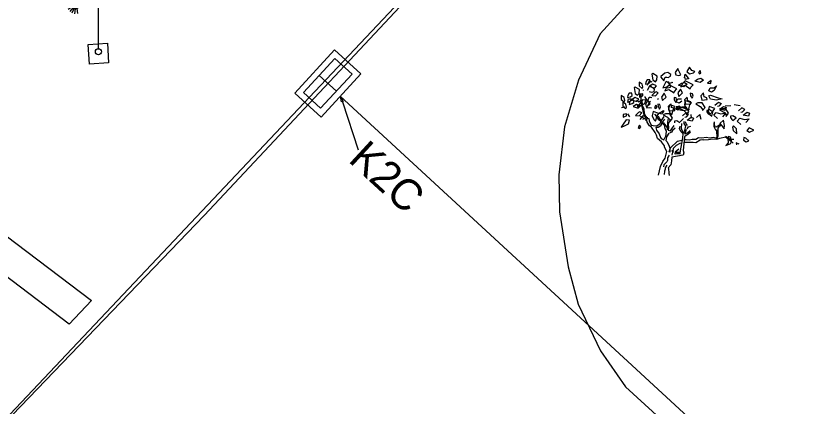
# Model space of a CAD drawing. Extents: x 343997 to 344255, y 298512 to 298767.
# Drawn here: x 344085.39 to 344111.1, y 298717.85 to 298730.51 of the extents above; entities that cross this region are included whole.
import ezdxf

# ---------------------------------------------------------------- set-up
doc = ezdxf.new("R2010")
doc.units = 0
for name, color, linetype in [('Default', 7, 'Continuous'), ('DH_CADRE-CARTOUCHE', 7, 'Continuous'), ('DIR-Projet VRD1', 7, 'Continuous'), ('GO_DALLE', 7, 'Continuous'), ('O-Projet New VRD', 7, 'Continuous'), ('PC_REBAR', 7, 'Continuous'), ('RES_ELECTRICITE', 7, 'Continuous')]:
    doc.layers.add(name, color=color, linetype=linetype)

# ---------------------------------------------------------------- blocks, each defined once
blk = doc.blocks.new('EDF1')
at = {"layer": 'Default'}
for points in [[(-0.0855, 0.1462), (-0.0985, 0.1373)], [(-0.083, 0.1422), (-0.0931, 0.1303)], [(-0.0793, 0.1397), (-0.086, 0.1257)], [(-0.0753, 0.1388), (-0.0781, 0.1235)], [(-0.0701, 0.14), (-0.0684, 0.1241)], [(0, 0.01), (0, 0.15)]]:
    blk.add_lwpolyline(points, dxfattribs=at)
for centre, radius in [((-0.075, 0.15), 0.0112), ((0, 0), 0.01)]:
    blk.add_circle(centre, radius, dxfattribs=at)
blk.add_arc((-0.035, 0.155), 0.0354, 351.8699, 171.8699, dxfattribs=at)
blk = doc.blocks.new('FLAMBOY')
at = {"layer": 'Default'}
for p, q in [((-0.0832, 0.3464), (-0.0832, 0.3442)), ((-0.0238, 0.3069), (-0.0213, 0.3132)), ((-0.157, 0.2764), (-0.1707, 0.2742)), ((0.2497, 0.2813), (0.2722, 0.2832)), ((0.3097, 0.2813), (0.2859, 0.2854)), ((-0.1371, 0.2378), (-0.1446, 0.2497)), ((0.0808, 0.2303), (0.0671, 0.2171)), ((0.0866, 0.1688), (0.0866, 0.1688)), ((0.0407, 0.0927), (0.0337, 0.1011))]:
    blk.add_line(p, q, dxfattribs=at)
for points in [[(0.0617, 0.4053), (0.0692, 0.4072), (0.0592, 0.4288), (0.0579, 0.4328), (0.0467, 0.4172), (0.0492, 0.4072)], [(0.1054, 0.4113), (0.1204, 0.415), (0.1267, 0.4213), (0.1142, 0.425), (0.1054, 0.4388), (0.0942, 0.4213)], [(0.1504, 0.415), (0.1479, 0.425), (0.1417, 0.4172), (0.1454, 0.4113)], [(-0.0621, 0.3722), (-0.0546, 0.3772), (-0.0558, 0.3872), (-0.0671, 0.3872), (-0.0721, 0.3772), (-0.0733, 0.3691)], [(-0.0471, 0.4106), (-0.0433, 0.3866), (-0.0333, 0.3791), (-0.0271, 0.3866), (-0.0258, 0.4025), (-0.0433, 0.4122)], [(0.0054, 0.4141), (-0.0108, 0.4006), (-0.0108, 0.3985), (0.0004, 0.3825), (0.0042, 0.3906), (0.0067, 0.3985), (0.0129, 0.3985), (0.0179, 0.3966), (0.0279, 0.4025), (0.0292, 0.4085), (0.0167, 0.4163)], [(0.0892, 0.3891), (0.0867, 0.395), (0.0842, 0.395), (0.0867, 0.4106), (0.0979, 0.395), (0.1017, 0.3928)], [(0.1504, 0.3938), (0.1617, 0.3863), (0.1479, 0.3763), (0.1267, 0.3822), (0.1379, 0.39)], [(-0.1195, 0.3564), (-0.1157, 0.3324), (-0.1057, 0.3249), (-0.0995, 0.3324), (-0.0982, 0.3483), (-0.1157, 0.358)], [(-0.0846, 0.3581), (-0.0871, 0.3697), (-0.0996, 0.3775), (-0.0996, 0.3622), (-0.0871, 0.3522)], [(-0.0433, 0.3691), (-0.0571, 0.361), (-0.0408, 0.355), (-0.0358, 0.355), (-0.0283, 0.3631)], [(0.0292, 0.3644), (0.0254, 0.3685), (0.0129, 0.3803), (0.0079, 0.3763), (-0.0008, 0.3606), (-0.0033, 0.3547), (0.0079, 0.3569), (0.0167, 0.3547), (0.0279, 0.3569)], [(0.0533, 0.35), (0.0371, 0.3581), (0.0221, 0.3656), (0.0121, 0.3562), (0.0046, 0.3421), (0.0208, 0.3481), (0.0421, 0.334), (0.0446, 0.3403)], [(0.0958, 0.3693), (0.0821, 0.3593), (0.0608, 0.3653), (0.0721, 0.3731), (0.0846, 0.3768)], [(0.1192, 0.3669), (0.1029, 0.375), (0.0879, 0.3825), (0.0779, 0.3731), (0.0704, 0.3591), (0.0867, 0.365), (0.1079, 0.351), (0.1104, 0.3572)], [(0.1779, 0.3738), (0.1917, 0.3716), (0.1929, 0.3838)], [(0.1829, 0.3422), (0.1892, 0.3541), (0.2042, 0.3541), (0.2142, 0.3622), (0.2054, 0.3441), (0.1942, 0.3366)], [(-0.172, 0.308), (-0.1595, 0.298), (-0.157, 0.3039), (-0.1595, 0.3155), (-0.172, 0.3233)], [(-0.1345, 0.318), (-0.127, 0.323), (-0.1282, 0.333), (-0.1395, 0.333), (-0.1445, 0.323), (-0.1457, 0.3149)], [(-0.0983, 0.3285), (-0.0983, 0.3166), (-0.0846, 0.3225), (-0.0846, 0.3306)], [(-0.0308, 0.3388), (-0.0358, 0.336), (-0.0483, 0.3241), (-0.0333, 0.3225), (-0.0221, 0.3341)], [(0.0108, 0.3168), (0.0021, 0.3325), (-0.0079, 0.3168), (-0.0042, 0.3031)], [(0.0767, 0.3338), (0.0679, 0.3494), (0.0579, 0.3338), (0.0617, 0.32)], [(0.1167, 0.3306), (0.1079, 0.3325), (0.1092, 0.3225), (0.1154, 0.3125), (0.1192, 0.3206)], [(0.1767, 0.3069), (0.1754, 0.3147), (0.1642, 0.3185), (0.1617, 0.3344), (0.1504, 0.3225), (0.1542, 0.305)], [(0.1829, 0.3225), (0.1904, 0.3244), (0.2204, 0.3147), (0.2367, 0.3106), (0.2142, 0.305), (0.1904, 0.3091)], [(-0.1504, 0.2768), (-0.1529, 0.2884), (-0.1654, 0.2962), (-0.1654, 0.2809), (-0.1529, 0.2709)], [(-0.1421, 0.3103), (-0.1308, 0.3103), (-0.1296, 0.3038), (-0.1446, 0.2953)], [(-0.1392, 0.2878), (-0.1279, 0.2909), (-0.1204, 0.2959), (-0.1217, 0.3059), (-0.1329, 0.3059), (-0.1379, 0.2959)], [(-0.1132, 0.3008), (-0.1082, 0.3008), (-0.1007, 0.3089), (-0.1157, 0.3149), (-0.1295, 0.3067)], [(-0.0958, 0.281), (-0.0758, 0.2906), (-0.0721, 0.3047), (-0.0858, 0.3066), (-0.0983, 0.2888), (-0.1058, 0.2772)], [(-0.07, 0.276), (-0.055, 0.2897), (-0.0638, 0.3053), (-0.0738, 0.2897)], [(0.03, 0.2903), (0.0187, 0.2785), (0.0225, 0.261), (0.045, 0.2628), (0.0437, 0.2707), (0.0325, 0.2744)], [(0.0508, 0.3137), (0.0421, 0.3156), (0.0433, 0.3056), (0.0496, 0.2956), (0.0533, 0.3037)], [(0.1108, 0.29), (0.1096, 0.2978), (0.0983, 0.3015), (0.0958, 0.3175), (0.0846, 0.3056), (0.0883, 0.2881)], [(0.1117, 0.2953), (0.1054, 0.2853), (0.0992, 0.2638), (0.0917, 0.2697), (0.0854, 0.2853), (0.0892, 0.3028)], [(0.1679, 0.2756), (0.1567, 0.2938), (0.1392, 0.2938), (0.1304, 0.2897), (0.1479, 0.2797), (0.1567, 0.27), (0.1579, 0.2622)], [(-0.1092, 0.2878), (-0.1229, 0.2796), (-0.1067, 0.2737), (-0.1017, 0.2737), (-0.0942, 0.2818)], [(-0.0967, 0.2574), (-0.1017, 0.2546), (-0.1142, 0.2428), (-0.0992, 0.2412), (-0.0879, 0.2528)], [(-0.0263, 0.2413), (-0.02, 0.2513), (-0.0425, 0.2588), (-0.0463, 0.2413), (-0.04, 0.2257), (-0.0325, 0.2197)], [(-0.0258, 0.2775), (-0.0321, 0.2841), (-0.0371, 0.2756), (-0.0321, 0.2706)], [(-0.015, 0.2866), (-0.0238, 0.2885), (-0.0225, 0.2785), (-0.0163, 0.2685), (-0.0125, 0.2766)], [(-0.0079, 0.2484), (-0.0179, 0.2525), (-0.0004, 0.2631), (-0.0004, 0.2584)], [(0.0396, 0.2684), (0.0458, 0.2784), (0.0233, 0.2859), (0.0196, 0.2684), (0.0258, 0.2528), (0.0333, 0.2468)], [(0.0579, 0.2653), (0.0654, 0.2753), (0.0654, 0.28), (0.0479, 0.2694)], [(0.0512, 0.2785), (0.0587, 0.2803), (0.0887, 0.2707), (0.105, 0.2666), (0.0825, 0.261), (0.0587, 0.265)], [(0.0733, 0.2768), (0.0646, 0.2728), (0.0821, 0.2628), (0.0908, 0.2531), (0.0921, 0.2453), (0.1021, 0.2587), (0.0908, 0.2768)], [(0.1804, 0.2497), (0.1854, 0.246), (0.1979, 0.2569), (0.1854, 0.2653), (0.1754, 0.2635), (0.1754, 0.2575)], [(0.2009, 0.2616), (0.2072, 0.2716), (0.1847, 0.2791), (0.1809, 0.2616), (0.1872, 0.246), (0.1947, 0.24)], [(0.2522, 0.27), (0.2347, 0.27), (0.2259, 0.266), (0.2434, 0.256), (0.2522, 0.2463), (0.2534, 0.2385), (0.2634, 0.2519)], [(0.2479, 0.2635), (0.2267, 0.2678), (0.2429, 0.2794), (0.2529, 0.2753)], [(-0.1617, 0.1996), (-0.1417, 0.2093), (-0.1379, 0.2234), (-0.1517, 0.2253), (-0.1642, 0.2074), (-0.1717, 0.1959)], [(-0.1642, 0.2471), (-0.1642, 0.2353), (-0.1504, 0.2412), (-0.1504, 0.2493)], [(0.0075, 0.2497), (-0.0013, 0.2457), (0.0162, 0.2357), (0.025, 0.226), (0.0262, 0.2182), (0.0362, 0.2316), (0.025, 0.2497)], [(0.1112, 0.2353), (0.1212, 0.2313), (0.1162, 0.2194), (0.095, 0.2238)], [(0.2759, 0.226), (0.2809, 0.2222), (0.2934, 0.2332), (0.2809, 0.2416), (0.2709, 0.2397), (0.2709, 0.2338)], [(0.3484, 0.2516), (0.3434, 0.2397), (0.3222, 0.2441), (0.3384, 0.2557)], [(-0.0917, 0.1962), (-0.0979, 0.2028), (-0.1029, 0.1943), (-0.0979, 0.1893)], [(0.2284, 0.2104), (0.2359, 0.2007), (0.2447, 0.1888), (0.2472, 0.2025), (0.2422, 0.2235)], [(0.2834, 0.201), (0.2784, 0.1957), (0.2822, 0.1813), (0.2972, 0.1688), (0.2959, 0.1882)], [(0.3659, 0.1835), (0.3472, 0.1925), (0.3372, 0.1819), (0.3484, 0.175)], [(0.2522, 0.1216), (0.2722, 0.1294), (0.2747, 0.1394), (0.2709, 0.155), (0.2622, 0.1569), (0.2597, 0.1491), (0.2609, 0.1316)], [(0.3334, 0.151), (0.3247, 0.1532), (0.3234, 0.1432), (0.3347, 0.1354), (0.3447, 0.1394)]]:
    blk.add_lwpolyline(points, close=True, dxfattribs=at)
for points in [[(-0.0579, 0.34), (-0.0492, 0.3378), (-0.0379, 0.34), (-0.0367, 0.3475), (-0.0404, 0.3515), (-0.0529, 0.3634), (-0.0579, 0.3593), (-0.0667, 0.3437)], [(-0.0654, 0.3656), (-0.0617, 0.3737), (-0.0592, 0.3815), (-0.0529, 0.3815), (-0.0479, 0.3796)], [(0.0321, 0.3781), (0.0358, 0.3759), (0.0233, 0.3721), (0.0208, 0.3781), (0.0183, 0.3781)], [(-0.0719, 0.2357), (-0.0785, 0.2441), (-0.0834, 0.261), (-0.0916, 0.2965), (-0.0916, 0.315), (-0.0916, 0.3302)], [(-0.1092, 0.3053), (-0.0992, 0.2978), (-0.0929, 0.3053)], [(-0.0883, 0.3049), (-0.0867, 0.2846), (-0.0801, 0.2694), (-0.0785, 0.2509), (-0.0686, 0.2323), (-0.0604, 0.2306), (-0.0588, 0.2205), (-0.0506, 0.2036), (-0.0424, 0.2019), (-0.0276, 0.2002), (-0.0145, 0.2103), (-0.0079, 0.2221), (0.002, 0.239)], [(-0.0767, 0.3193), (-0.0767, 0.3171), (-0.0654, 0.3012), (-0.0617, 0.3093), (-0.0592, 0.3171), (-0.0529, 0.3171), (-0.0479, 0.3153)], [(-0.0529, 0.299), (-0.0579, 0.2949), (-0.0667, 0.2793), (-0.0692, 0.2734), (-0.0579, 0.2756), (-0.0492, 0.2734)], [(0.0737, 0.3), (0.0625, 0.2925), (0.0512, 0.2982), (0.0575, 0.31), (0.0725, 0.31)], [(0.2079, 0.285), (0.2217, 0.2969), (0.2329, 0.291), (0.2242, 0.281), (0.2179, 0.2794)], [(-0.0945, 0.2799), (-0.1032, 0.2846), (-0.1082, 0.2817)], [(0.3134, 0.2557), (0.3197, 0.2572), (0.3284, 0.2672), (0.3172, 0.2732), (0.3034, 0.2613)], [(-0.0846, 0.2281), (-0.0683, 0.2363), (-0.0846, 0.2413), (-0.0958, 0.2266)], [(-0.021, 0.0009), (-0.0128, 0.0364), (-0.003, 0.0566), (0.0069, 0.0701), (0.0134, 0.0972), (0.0036, 0.1141), (0.0036, 0.1191), (-0.0079, 0.136), (-0.0243, 0.1495), (-0.0292, 0.163), (-0.0341, 0.1732), (-0.0489, 0.1951), (-0.0571, 0.2002), (-0.067, 0.2154), (-0.0686, 0.2255), (-0.0932, 0.239)], [(-0.0663, 0.236), (-0.0663, 0.2313), (-0.0738, 0.2213)], [(-0.0112, 0.2188), (-0.0194, 0.2255), (-0.0276, 0.239), (-0.0358, 0.2475)], [(0.0036, 0.2272), (-0.0079, 0.212), (-0.0112, 0.2002), (-0.0227, 0.1934), (-0.0309, 0.1934), (-0.0292, 0.1833), (-0.0177, 0.1681), (-0.0128, 0.1529), (-0.0095, 0.1495), (0.0003, 0.1445), (0.0069, 0.1546), (0.0085, 0.158), (0.0118, 0.1782), (0.0069, 0.1901), (0.0036, 0.2036), (-0.0062, 0.2103)], [(-0.0227, 0.2407), (-0.0161, 0.2289), (-0.0095, 0.2205)], [(-0.0013, 0.2137), (0.0085, 0.2002), (0.0151, 0.1901), (0.0151, 0.185), (0.0167, 0.2002), (0.0167, 0.2154), (0.02, 0.2323)], [(0.0862, 0.2353), (0.0925, 0.2369), (0.1012, 0.2469), (0.09, 0.2528), (0.0762, 0.241)], [(0.1096, 0.2465), (0.1096, 0.2406), (0.1146, 0.2328)], [(0.1517, 0.2263), (0.1467, 0.2472), (0.1329, 0.2341)], [(0.2179, 0.23), (0.2029, 0.2438), (0.2129, 0.2553), (0.2317, 0.2497), (0.2517, 0.2535), (0.2379, 0.2378)], [(0.3134, 0.2063), (0.2984, 0.22), (0.3084, 0.2316), (0.3272, 0.226), (0.3472, 0.2297), (0.3334, 0.2141)], [(0.0249, 0.2221), (0.0184, 0.2069), (0.02, 0.1934), (0.0184, 0.1833), (0.0282, 0.1799), (0.0331, 0.1884), (0.043, 0.2019)], [(0.0662, 0.2128), (0.0537, 0.2213), (0.0437, 0.2194), (0.0437, 0.2135)], [(0.0619, 0.106), (0.0466, 0.0939), (0.0454, 0.0878), (0.0666, 0.0915), (0.0783, 0.1519), (0.0795, 0.1688), (0.0701, 0.1773), (0.0642, 0.1894), (0.0666, 0.199)], [(0.0725, 0.2099), (0.0713, 0.1918), (0.076, 0.1761), (0.0819, 0.1724), (0.0866, 0.1833), (0.0901, 0.199), (0.083, 0.2099), (0.083, 0.2184)], [(0.204, 0.2135), (0.204, 0.1978), (0.2099, 0.1845), (0.2146, 0.1845), (0.2146, 0.1712), (0.2157, 0.1628), (0.2157, 0.1543), (0.2122, 0.1507), (0.2005, 0.1531), (0.1876, 0.1507), (0.1723, 0.1531), (0.1547, 0.1507), (0.1418, 0.1519), (0.13, 0.1459), (0.1159, 0.1459), (0.103, 0.1422), (0.0912, 0.1446), (0.0819, 0.1434)], [(0.0877, 0.2184), (0.0912, 0.2075), (0.0959, 0.2015)], [(0.0948, 0.1882), (0.1006, 0.1966), (0.11, 0.199)], [(0.2298, 0.2063), (0.2193, 0.199), (0.2134, 0.1954), (0.2087, 0.1966), (0.2063, 0.2075), (0.2063, 0.2172)], [(0.2169, 0.1483), (0.2204, 0.1604), (0.2204, 0.1797), (0.2204, 0.1906), (0.2263, 0.199), (0.2345, 0.2039)], [(0.0208, 0.1712), (0.0114, 0.1555), (0.009, 0.141), (0.0137, 0.1374), (0.0208, 0.1217), (0.0255, 0.1096), (0.0255, 0.0939), (0.0231, 0.0951), (0.0278, 0.112), (0.056, 0.1386), (0.0736, 0.1422)], [(0.1089, 0.1749), (0.0983, 0.1652), (0.0912, 0.1616), (0.0842, 0.1567), (0.0795, 0.1011), (0.0819, 0.0915), (0.0795, 0.0818), (0.0337, 0.0733), (0.0313, 0.0588), (0.029, 0.0431), (0.0184, 0.031), (0.0196, 0.0274), (0.0208, 0.0093), (0.0231, -0.0001)], [(0.0463, 0.1917), (0.0364, 0.1816), (0.0315, 0.1749), (0.0233, 0.1715)], [(0.0912, 0.1857), (0.0866, 0.1688), (0.0971, 0.1724), (0.1077, 0.1821)], [(0.0384, 0.0975), (0.0396, 0.1096), (0.0525, 0.1217), (0.0666, 0.1301), (0.0736, 0.1314)], [(0.0854, 0.1338), (0.1053, 0.135), (0.1194, 0.135), (0.13, 0.1326), (0.1476, 0.1434), (0.1594, 0.1459), (0.1629, 0.1446), (0.1817, 0.1459), (0.1981, 0.1483), (0.2157, 0.1471), (0.2275, 0.1507), (0.251, 0.1567), (0.2557, 0.1519), (0.2733, 0.1386), (0.2815, 0.1301)], [(0.251, 0.1592), (0.2721, 0.1459), (0.2768, 0.1471), (0.2803, 0.1471), (0.2839, 0.1471)], [(0.3059, 0.1257), (0.2934, 0.1316), (0.2947, 0.1235)], [(0.0349, 0.0818), (0.0372, 0.0939), (0.0396, 0.1011)], [(0.022, 0.0818), (0.0161, 0.0709), (0.0161, 0.06), (0.0137, 0.0552), (0.0102, 0.0516), (0.0008, 0.0431), (-0.0004, 0.0347)], [(0.049, 0.0866), (0.0619, 0.0891), (0.0678, 0.0891)], [(0.0501, 0.0939), (0.0607, 0.0939), (0.0689, 0.0939)], [(0.0137, 0.0407), (0.0067, 0.031), (0.0067, 0.025), (0.0032, 0.0165), (0.002, 0.0032)]]:
    blk.add_lwpolyline(points, dxfattribs=at)

msp = doc.modelspace()

# ---------------------------------------------------------------- linework, layer by layer
at = {"layer": 'DH_CADRE-CARTOUCHE'}
for points in [[(344035.538, 298697.865), (344038.262, 298695.856), (344041.267, 298693.813), (344044.479, 298691.842), (344047.664, 298690.365), (344050.648, 298689.339), (344052.822, 298689.099), (344054.599, 298689.128), (344056.124, 298689.428), (344057.609, 298690.129), (344058.956, 298690.85), (344060.299, 298691.725), (344061.274, 298692.556), (344063.092, 298694.498), (344091.5, 298724.03), (344099.786, 298732.889), (344115.711, 298749.674), (344119.028, 298753.296)], [(344122.649, 298749.916), (344119.175, 298746.216), (344104.333, 298729.921), (344103.629, 298728.425), (344103.178, 298726.908), (344102.994, 298725.349), (344103.009, 298724.152), (344103.293, 298722.366), (344103.622, 298721.156), (344104.336, 298719.642), (344105.154, 298718.475), (344128.542, 298697.099), (344156.76, 298672.229), (344158.923, 298671.699), (344160.816, 298671.605), (344163.478, 298672.279), (344165.611, 298673.484), (344167.1, 298674.65), (344168.229, 298675.97), (344184.084, 298692.584)]]:
    msp.add_lwpolyline(points, dxfattribs=at)
at = {"layer": 'DIR-Projet VRD1'}
msp.add_line((344095.906, 298727.904), (344127.79, 298698.478), dxfattribs=at)
msp.add_lwpolyline([(344102.789, 298736.23), (344059.183, 298690.031)], dxfattribs=at)
at = {"layer": 'GO_DALLE'}
msp.add_lwpolyline([(344068.796, 298733.503), (344071.254, 298731.258), (344073.247, 298732.35), (344087.843, 298721.279), (344087.121, 298720.51), (344076.382, 298728.667), (344073.692, 298725.643), (344072.914, 298726.336), (344075.504, 298729.312), (344073.248, 298731.046), (344072.159, 298730.47), (344072.928, 298729.686), (344071.196, 298727.705)], dxfattribs=at)
msp.add_lwpolyline([(344087.741, 298729.577), (344088.359, 298729.62), (344088.397, 298728.981), (344087.785, 298728.939)], close=True, dxfattribs=at)
at = {"layer": 'O-Projet New VRD'}
msp.add_line((344095.228, 298728.57), (344095.78, 298728.062), dxfattribs=at)
for points in [[(344094.437, 298728.006), (344095.724, 298729.405), (344096.57, 298728.626), (344095.283, 298727.227)], [(344094.72, 298728.018), (344095.736, 298729.122), (344096.288, 298728.614), (344095.272, 298727.51)], [(344095.947, 298727.715), (344095.92, 298727.896), (344096.004, 298727.734)]]:
    msp.add_lwpolyline(points, close=True, dxfattribs=at)
msp.add_lwpolyline([(344095.976, 298727.724), (344096.484, 298726.164)], dxfattribs=at)

# ---------------------------------------------------------------- block references
at = {"layer": 'PC_REBAR', "xscale": 8, "yscale": 8}
msp.add_blockref('FLAMBOY', (344106.386, 298725.336), dxfattribs=at)
at = {"layer": 'RES_ELECTRICITE', "xscale": 10, "yscale": 10}
msp.add_blockref('EDF1', (344088.071, 298729.343), dxfattribs=at)

# ---------------------------------------------------------------- texts
at = {"layer": 'O-Projet New VRD'}
msp.add_text('K2C', height=1.0003, rotation=317.3672, dxfattribs=at).set_placement((344096.134, 298725.805))

doc.saveas('drawing.dxf')
